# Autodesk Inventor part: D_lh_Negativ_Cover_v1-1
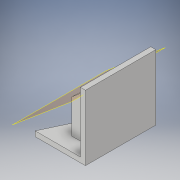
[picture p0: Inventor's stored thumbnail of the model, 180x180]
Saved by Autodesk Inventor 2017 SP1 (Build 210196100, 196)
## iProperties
Part Number: D_lh_Negativ_Cover_v1-1
Material: Generisch
Document SubType Name: Modeling
Designer: haesner
Density: 1 g/cm^3
Appearance: Vorgabe
Part Number: D_lh_Negativ_Cover_v1-1_3D-Druck
Author: haesner
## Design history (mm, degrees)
sketch "Skizze1"
  geometry: L1 (0, 14)-(0, -14); L2 (0, -19.6)-(0, 19.6) reference; L3 (0, 14)-(-4.943, 14); L4 (-4.943, 14)-(-18, -14); L5 (-18, -14)-(0, -14); L6 (-21.6, 0)-(3.6, 0) reference; 1 further point
  constraints: 8 end point, 1 collinear, 1 horizontal, 1 parallel, 1 vertical, 1 other
  dimensions: "d23" = 28 distance of L1.start L1.end; "d24" = 25 deg angle of L1 L4; "d25" = 18 distance of L4.end L1.end
extrude "Extrusion1" new body sketch "Skizze1" distance "d1" = 2; taper "d2" = 0 deg
sketch "Skizze2"
  geometry: L1 (0, 8.5)-(-1, 8.5); L2 (-1, 8.5)-(-8.927, -8.5); L3 (-8.927, -8.5)-(0, -8.5); L4 (0, 8.5)-(0, -8.5); L5 (-21.6, 0)-(3.6, 0) reference; L6 (0, -19.6)-(0, 19.6) reference; L7 (0, -14)-(0, 14) reference; 1 further point
  constraints: 8 end point, 1 collinear, 1 horizontal, 1 parallel, 1 other
  dimensions: "d3" = 1 distance of L1.start L1.end; "d4" = 17 distance of L1.start L3.end; "d5" = 25 deg angle of L4 L2
extrude "Extrusion2" join sketch "Skizze2" distance "d7" = 21; taper "d8" = 0 deg
workplane "Arbeitsebene1"
feature "Trennen1"
sketch "Skizze3"
  geometry: L1 (0, 28)-(0, 0) reference; L2 (0, 0)-(-26, 0); L3 (-26, 0)-(-26, 28); L4 (-26, 28)-(0, 28); L5 (0, 28)-(0, 0); L6 (5.2, 14)-(-31.2, 14) reference; 1 further point
  constraints: 8 end point, 2 parallel, 1 horizontal, 1 perpendicular, 1 point on line, 1 other
  dimensions: "d10" = 28 distance between parallel lines of L4 L2; "d11" = 26 distance between parallel lines of L1 L3
extrude "Extrusion3" join sketch "Skizze3" distance "d12" = 2; taper "d13" = 0 deg
node "Volumenkörper1"
other parameters: "d9" = -40 deg
